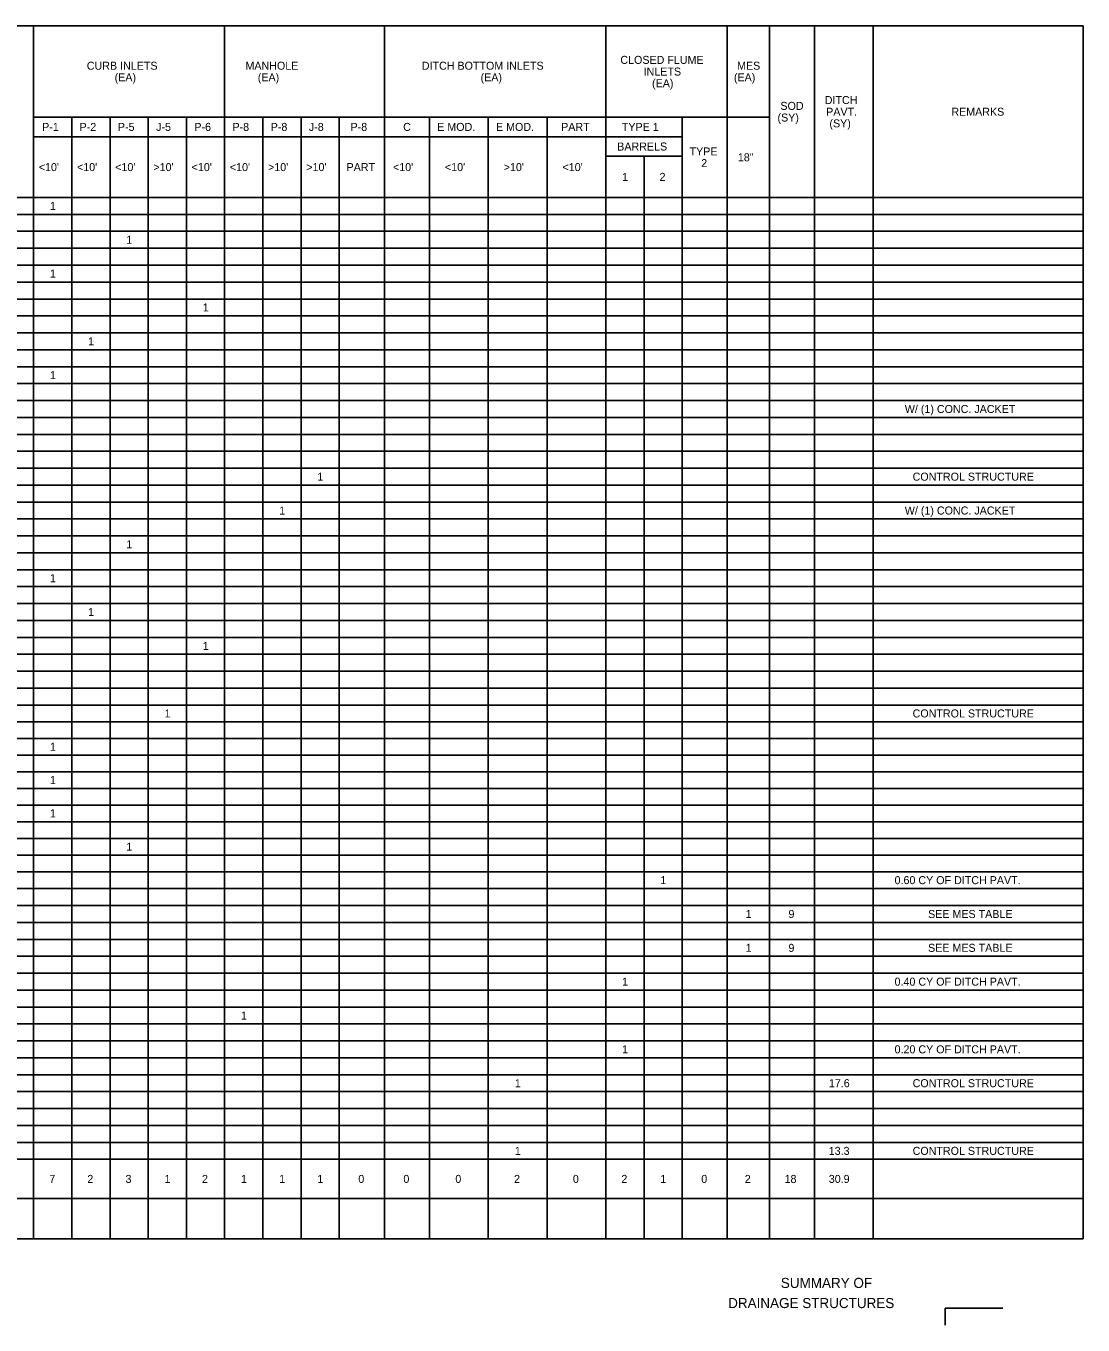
# Model space of a CAD drawing. Extents: x 0 to 765, y -1227 to 479.
# Drawn here: x 360 to 764.5, y -26.1 to 471 of the extents above; entities that cross this region are included whole.
import ezdxf

# ---------------------------------------------------------------- set-up
doc = ezdxf.new("R2010")
doc.units = 0
for name, color, linetype in [('Default', 7, 'Continuous'), ('Miscellaneous0', 7, 'Continuous'), ('PlotBorder_dp', 7, 'Continuous'), ('SheetLines_dp', 7, 'Continuous'), ('TextMinor', 7, 'Continuous'), ('TextShtNo', 7, 'Continuous')]:
    doc.layers.add(name, color=color, linetype=linetype)

msp = doc.modelspace()

# ---------------------------------------------------------------- linework, layer by layer
at = {"layer": 'PlotBorder_dp'}
for p, q in [((362.91, 471.05), (362.91, 405.42)), ((362.91, 471.05), (362.91, 6.97)), ((436.04, 471.05), (436.04, 436.17)), ((497.16, 471.05), (497.16, 6.97)), ((497.16, 471.05), (497.16, 6.97)), ((581.91, 471.05), (581.91, 421.17)), ((581.91, 471.05), (581.91, 6.97)), ((628.41, 471.05), (628.41, 398.95)), ((628.41, 471.05), (628.41, 6.97)), ((644.54, 471.05), (644.54, 6.97)), ((644.54, 471.05), (644.54, 6.97)), ((661.79, 471.05), (661.79, 6.97)), ((661.79, 471.05), (661.79, 6.97)), ((684.29, 471.05), (684.29, 405.42)), ((684.29, 471.05), (684.29, 6.97)), ((362.91, 436.17), (644.54, 436.17)), ((362.91, 436.17), (644.54, 436.17)), ((377.54, 436.17), (377.54, 405.42)), ((377.54, 436.17), (377.54, 6.97)), ((392.16, 436.17), (392.16, 405.42)), ((392.16, 436.17), (392.16, 6.97)), ((406.79, 436.17), (406.79, 6.97)), ((406.79, 436.17), (406.79, 6.97)), ((421.41, 436.17), (421.41, 6.97)), ((421.41, 436.17), (421.41, 6.97)), ((436.04, 436.17), (436.04, 6.97)), ((450.66, 436.17), (450.66, 6.97)), ((450.66, 436.17), (450.66, 6.97)), ((465.29, 436.17), (465.29, 6.97)), ((465.29, 436.17), (465.29, 6.97)), ((479.91, 436.17), (479.91, 6.97)), ((479.91, 436.17), (479.91, 6.97)), ((514.41, 436.17), (514.41, 6.97)), ((514.41, 436.17), (514.41, 6.97)), ((536.91, 436.17), (536.91, 6.97)), ((536.91, 436.17), (536.91, 6.97)), ((559.41, 436.17), (559.41, 6.97)), ((559.41, 436.17), (559.41, 6.97)), ((611.16, 436.17), (611.16, 398.95)), ((611.16, 436.17), (611.16, 6.97)), ((362.91, 428.67), (559.41, 428.67)), ((362.91, 428.67), (611.16, 428.67)), ((436.04, 428.67), (436.04, 6.97)), ((581.91, 428.67), (611.16, 428.67)), ((581.91, 421.17), (611.16, 421.17)), ((596.54, 421.17), (596.54, 398.95)), ((596.54, 421.17), (596.54, 6.97)), ((581.91, 405.42), (581.91, 6.97)), ((596.54, 147.42), (596.54, 6.97)), ((611.16, 147.42), (611.16, 6.97)), ((628.41, 147.42), (628.41, 6.97)), ((0.29, 37.35), (764.54, 37.35)), ((362.91, 37.35), (362.91, 6.97)), ((377.54, 37.35), (377.54, 6.97)), ((392.16, 37.35), (392.16, 6.97)), ((684.29, 37.35), (684.29, 6.97)), ((85.04, 22.35), (764.54, 22.35)), ((85.04, 22.35), (764.54, 22.35))]:
    msp.add_line(p, q, dxfattribs=at)
at = {"layer": 'SheetLines_dp'}
for p, q in [((0.29, 471.05), (764.54, 471.05)), ((764.54, 471.05), (764.54, 6.97)), ((0.29, 405.42), (764.54, 405.42)), ((0.29, 405.42), (764.54, 405.42)), ((0.29, 6.97), (764.54, 6.97))]:
    msp.add_line(p, q, dxfattribs=at)
at = {"layer": 'TextMinor'}
for p, q in [((0.29, 398.95), (764.54, 398.95)), ((684.29, 398.95), (764.54, 398.95)), ((0.29, 392.47), (764.54, 392.47)), ((0.29, 392.47), (764.54, 392.47)), ((0.29, 386), (764.54, 386)), ((12.29, 386), (764.54, 386)), ((0.29, 379.52), (764.54, 379.52)), ((0.29, 379.52), (764.54, 379.52)), ((0.29, 373.05), (764.54, 373.05)), ((12.29, 373.05), (764.54, 373.05)), ((0.29, 366.57), (764.54, 366.57)), ((0.29, 366.57), (764.54, 366.57)), ((0.29, 360.1), (764.54, 360.1)), ((12.29, 360.1), (764.54, 360.1)), ((0.29, 353.62), (764.54, 353.62)), ((0.29, 353.62), (764.54, 353.62)), ((0.29, 347.15), (764.54, 347.15)), ((12.29, 347.15), (764.54, 347.15)), ((0.29, 340.67), (764.54, 340.67)), ((0.29, 340.67), (764.54, 340.67)), ((0.29, 334.2), (764.54, 334.2)), ((12.29, 334.2), (764.54, 334.2)), ((0.29, 327.72), (764.54, 327.72)), ((0.29, 327.72), (764.54, 327.72)), ((0.29, 321.25), (764.54, 321.25)), ((12.29, 321.25), (764.54, 321.25)), ((0.29, 314.77), (764.54, 314.77)), ((0.29, 314.77), (764.54, 314.77)), ((0.29, 308.3), (764.54, 308.3)), ((12.29, 308.3), (764.54, 308.3)), ((0.29, 301.82), (764.54, 301.82)), ((0.29, 301.82), (764.54, 301.82)), ((0.29, 295.35), (764.54, 295.35)), ((12.29, 295.35), (764.54, 295.35)), ((0.29, 288.87), (764.54, 288.87)), ((0.29, 288.87), (764.54, 288.87)), ((0.29, 282.4), (764.54, 282.4)), ((12.29, 282.4), (764.54, 282.4)), ((0.29, 275.92), (764.54, 275.92)), ((0.29, 275.92), (764.54, 275.92)), ((0.29, 269.45), (764.54, 269.45)), ((12.29, 269.45), (764.54, 269.45)), ((0.29, 262.97), (764.54, 262.97)), ((0.29, 262.97), (764.54, 262.97)), ((0.29, 256.5), (764.54, 256.5)), ((12.29, 256.5), (764.54, 256.5)), ((0.29, 250.02), (764.54, 250.02)), ((0.29, 250.02), (764.54, 250.02)), ((0.29, 243.55), (764.54, 243.55)), ((12.29, 243.55), (764.54, 243.55)), ((0.29, 237.07), (764.54, 237.07)), ((0.29, 237.07), (764.54, 237.07)), ((0.29, 230.6), (764.54, 230.6)), ((12.29, 230.6), (764.54, 230.6)), ((0.29, 224.12), (764.54, 224.12)), ((0.29, 224.12), (764.54, 224.12)), ((0.29, 217.65), (764.54, 217.65)), ((12.29, 217.65), (764.54, 217.65)), ((0.29, 211.17), (764.54, 211.17)), ((0.29, 211.17), (764.54, 211.17)), ((0.29, 204.8), (764.54, 204.8)), ((12.29, 204.8), (764.54, 204.8)), ((0.29, 198.42), (764.54, 198.42)), ((0.29, 198.42), (764.54, 198.42)), ((0.29, 192.05), (764.54, 192.05)), ((12.29, 192.05), (764.54, 192.05)), ((0.29, 185.67), (764.54, 185.67)), ((0.29, 185.67), (764.54, 185.67)), ((0.29, 179.3), (764.54, 179.3)), ((12.29, 179.3), (764.54, 179.3)), ((0.29, 172.92), (764.54, 172.92)), ((0.29, 172.92), (764.54, 172.92)), ((0.29, 166.55), (764.54, 166.55)), ((12.29, 166.55), (764.54, 166.55)), ((0.29, 160.17), (764.54, 160.17)), ((0.29, 160.17), (764.54, 160.17)), ((0.29, 153.8), (764.54, 153.8)), ((12.29, 153.8), (764.54, 153.8)), ((0.29, 147.42), (764.54, 147.42)), ((0.29, 147.42), (764.54, 147.42)), ((0.29, 140.95), (764.54, 140.95)), ((0.29, 140.95), (764.54, 140.95)), ((0.29, 134.47), (764.54, 134.47)), ((0.29, 134.47), (764.54, 134.47)), ((0.29, 128), (764.54, 128)), ((0.29, 128), (764.54, 128)), ((0.29, 121.52), (764.54, 121.52)), ((0.29, 121.52), (764.54, 121.52)), ((0.29, 115.05), (764.54, 115.05)), ((0.29, 115.05), (764.54, 115.05)), ((0.29, 108.57), (764.54, 108.57)), ((0.29, 108.57), (764.54, 108.57)), ((0.29, 102.1), (764.54, 102.1)), ((0.29, 102.1), (764.54, 102.1)), ((0.29, 95.62), (764.54, 95.62)), ((0.29, 95.62), (764.54, 95.62)), ((0.29, 89.15), (764.54, 89.15)), ((0.29, 89.15), (764.54, 89.15)), ((0.29, 82.67), (764.54, 82.67)), ((0.29, 82.67), (764.54, 82.67)), ((0.29, 76.2), (764.54, 76.2)), ((0.29, 76.2), (764.54, 76.2)), ((0.29, 69.72), (764.54, 69.72)), ((0.29, 69.72), (764.54, 69.72)), ((0.29, 63.25), (764.54, 63.25)), ((0.29, 63.25), (764.54, 63.25)), ((0.29, 56.77), (764.54, 56.77)), ((0.29, 56.77), (764.54, 56.77)), ((0.29, 50.3), (764.54, 50.3)), ((0.29, 50.3), (764.54, 50.3)), ((0.29, 43.82), (764.54, 43.82)), ((0.29, 43.82), (764.54, 43.82)), ((0.29, 37.35), (764.54, 37.35))]:
    msp.add_line(p, q, dxfattribs=at)
at = {"layer": 'TextShtNo'}
for q in [(733.9, -19.58), (711.76, -26.06)]:
    msp.add_line((711.76, -19.58), q, dxfattribs=at)

# ---------------------------------------------------------------- texts
at = {"layer": 'Default'}
for s, height, p in [('SUMMARY OF', 3.855, (648.89, -11.88)), ('DRAINAGE STRUCTURES', 3.8546, (628.73, -19.58))]:
    msp.add_text(s, height=height, dxfattribs=at).set_placement(p)
at = {"layer": 'Miscellaneous0'}
for s, height, p in [('CURB INLETS', 3.0625, (383.28, 454.31)), ('MANHOLE ', 3.062, (444, 454.31)), ('DITCH BOTTOM INLETS', 3.0625, (511.48, 454.31)), ('CLOSED FLUME', 3.0625, (587.48, 456.54)), ('MES', 3.062, (632.14, 454.31)), ('(EA)', 3.062, (393.93, 449.85)), ('(EA)', 3.062, (448.72, 449.85)), ('(EA)', 3.062, (533.99, 449.85)), ('INLETS', 3.062, (596.38, 452.08)), ('(EA)', 3.062, (630.93, 449.85)), ('(EA)', 3.062, (599.61, 447.62)), ('DITCH', 3.062, (665.69, 441.17)), ('(SY)', 3.062, (647.61, 434.47)), ('SOD', 3.062, (648.73, 438.94)), ('PAVT.', 3.062, (666.24, 436.7)), ('REMARKS', 3.062, (714.15, 436.7)), ('P-1', 3.062, (366.18, 430.89)), ('P-2', 3.062, (380.51, 430.89)), ('P-5', 3.062, (395.18, 430.89)), ('J-5', 3.062, (409.8, 430.89)), ('P-6', 3.062, (424.45, 430.89)), ('P-8', 3.062, (439.02, 430.89)), ('P-8', 3.062, (453.65, 430.89)), ('J-8', 3.062, (468.27, 430.89)), ('P-8', 3.062, (484.21, 430.89)), ('C', 3.06, (504.35, 430.89)), ('E MOD.', 3.062, (517.38, 430.89)), ('E MOD.', 3.062, (539.88, 430.89)), ('PART', 3.062, (564.81, 430.89)), ('TYPE 1', 3.062, (588.05, 430.89)), ('(SY)', 3.062, (667.49, 432.24)), ('BARRELS', 3.062, (586.27, 423.39)), ('TYPE', 3.062, (613.96, 421.5)), ("<10'", 3.062, (364.9, 415.52)), ("<10'", 3.062, (379.52, 415.52)), ("<10'", 3.062, (394.15, 415.52)), (">10'", 3.062, (408.77, 415.52)), ("<10'", 3.062, (423.4, 415.52)), ("<10'", 3.062, (438.02, 415.52)), (">10'", 3.062, (452.65, 415.52)), (">10'", 3.062, (467.27, 415.52)), ('PART', 3.062, (482.69, 415.52)), ("<10'", 3.062, (500.46, 415.52)), ("<10'", 3.062, (520.34, 415.52)), (">10'", 3.062, (542.84, 415.52)), ("<10'", 3.062, (565.34, 415.52)), ('2', 3.06, (618.42, 417.04)), ('18"', 3.062, (632.44, 419.27)), ('1', 3.06, (588.15, 411.77)), ('2', 3.06, (602.48, 411.77)), ('1', 3.06, (369.15, 400.65)), ('1', 3.06, (398.4, 387.7)), ('1', 3.06, (369.15, 374.75)), ('1', 3.06, (427.65, 361.8)), ('1', 3.06, (383.77, 348.85)), ('1', 3.06, (369.15, 335.9)), ('W/ (1) CONC. JACKET', 3.0625, (696.33, 322.95)), ('1', 3.06, (471.52, 297.05)), ('CONTROL STRUCTURE', 3.0625, (699.32, 297.05)), ('1', 3.06, (456.9, 284.1)), ('W/ (1) CONC. JACKET', 3.0625, (696.33, 284.1)), ('1', 3.06, (398.4, 271.15)), ('1', 3.06, (369.15, 258.2)), ('1', 3.06, (383.77, 245.25)), ('1', 3.06, (427.65, 232.3)), ('1', 3.06, (413.02, 206.45)), ('CONTROL STRUCTURE', 3.0625, (699.32, 206.45)), ('1', 3.06, (369.15, 193.7)), ('1', 3.06, (369.15, 180.95)), ('1', 3.06, (369.15, 168.2)), ('1', 3.06, (398.4, 155.45)), ('1', 3.06, (602.77, 142.65)), ('0.60 CY OF DITCH PAVT.', 3.0625, (692.42, 142.65)), ('1', 3.06, (635.4, 129.7)), ('9', 3.06, (651.81, 129.7)), ('SEE MES TABLE', 3.0625, (705.24, 129.7)), ('1', 3.06, (635.4, 116.75)), ('9', 3.06, (651.81, 116.75)), ('SEE MES TABLE', 3.0625, (705.24, 116.75)), ('1', 3.06, (588.15, 103.8)), ('0.40 CY OF DITCH PAVT.', 3.0625, (692.42, 103.8)), ('1', 3.06, (442.27, 90.85)), ('1', 3.06, (588.15, 77.9)), ('0.20 CY OF DITCH PAVT.', 3.0625, (692.42, 77.9)), ('1', 3.06, (547.09, 64.95)), ('17.6', 3.062, (667.28, 64.95)), ('CONTROL STRUCTURE', 3.0625, (699.32, 64.95)), ('1', 3.06, (547.09, 39.05)), ('13.3', 3.062, (667.22, 39.05)), ('CONTROL STRUCTURE', 3.0625, (699.32, 39.05)), ('7', 3.06, (368.94, 28.32)), ('2', 3.06, (383.48, 28.32)), ('3', 3.06, (398.1, 28.32)), ('1', 3.06, (413.02, 28.32)), ('2', 3.06, (427.35, 28.32)), ('1', 3.06, (442.27, 28.32)), ('1', 3.06, (456.9, 28.32)), ('1', 3.06, (471.52, 28.32)), ('0', 3.06, (487.19, 28.32)), ('0', 3.06, (504.44, 28.32)), ('0', 3.06, (524.32, 28.32)), ('2', 3.06, (546.79, 28.32)), ('0', 3.06, (569.32, 28.32)), ('2', 3.06, (587.85, 28.32)), ('1', 3.06, (602.77, 28.32)), ('0', 3.06, (618.44, 28.32)), ('2', 3.06, (635.1, 28.32)), ('18', 3.062, (650.32, 28.32)), ('30.9', 3.062, (667.24, 28.32))]:
    msp.add_text(s, height=height, dxfattribs=at).set_placement(p)

doc.saveas('drawing.dxf')
